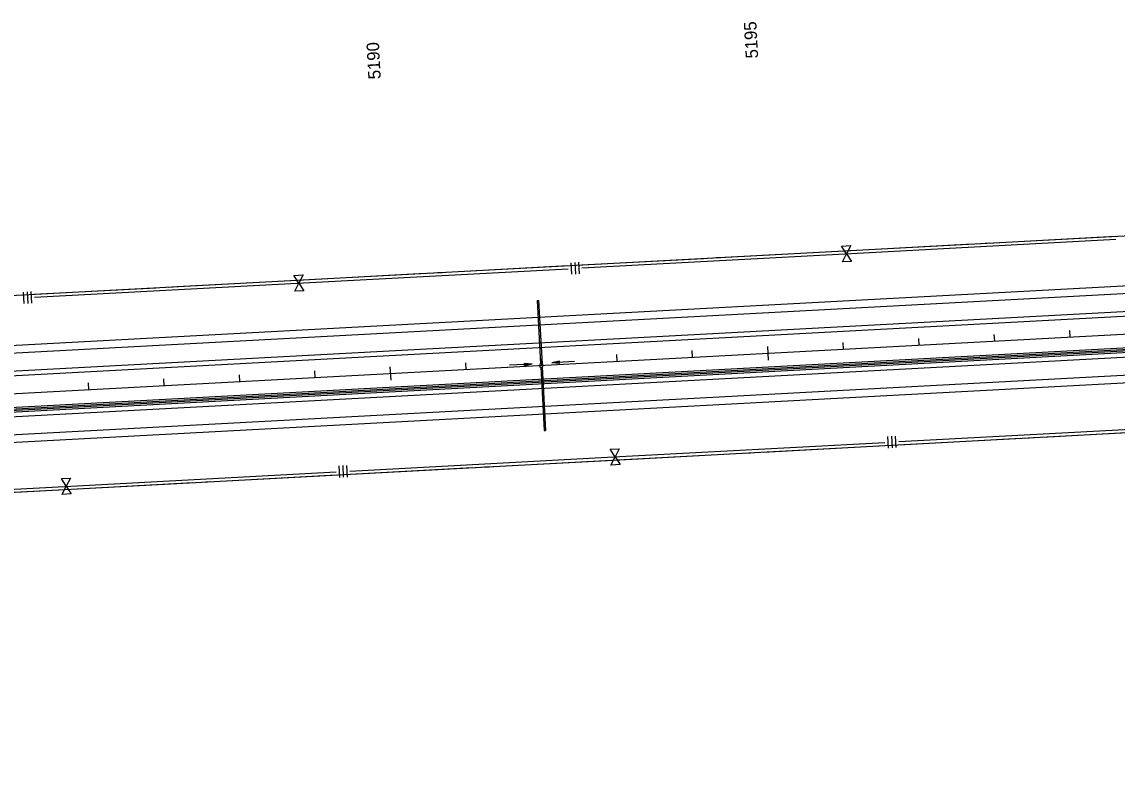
# Model space of a CAD drawing. Extents: x 192699 to 285914, y 194342 to 233219.
# Drawn here: x 263139 to 264587, y 224942 to 225937 of the extents above; entities that cross this region are included whole.
import ezdxf

# ---------------------------------------------------------------- set-up
doc = ezdxf.new("R2010")
doc.units = 0
for name, color, linetype in [('CENT LINE', 7, 'Continuous'), ('CONCRETE', 7, 'Continuous'), ('DRAINAGE', 7, 'Continuous'), ('DRAINAGE ARROWS', 7, 'Continuous'), ('R-W - CofA', 7, 'Continuous'), ('R_Water Annot', 7, 'Continuous'), ('ROAD', 7, 'Continuous'), ('SHOULDER', 7, 'Continuous'), ('STATIONING1', 7, 'Continuous'), ('WRSF', 7, 'Continuous')]:
    doc.layers.add(name, color=color, linetype=linetype)

msp = doc.modelspace()

# ---------------------------------------------------------------- linework, layer by layer
at = {"layer": 'CENT LINE'}
msp.add_line((253740.3, 224942.3), (269263.7, 225774), dxfattribs=at)
at = {"layer": 'CONCRETE'}
for p, q in [((262014.4, 225367.6), (265424.6, 225550.3)), ((262014.5, 225363.6), (265424.8, 225546.3))]:
    msp.add_line(p, q, dxfattribs=at)
at = {"layer": 'DRAINAGE'}
for p, q in [((263820.2, 225568.5), (263824.7, 225484.6)), ((263822.2, 225568.6), (263826.7, 225484.7)), ((263824.9, 225480.6), (263829.4, 225396.7)), ((263826.9, 225480.7), (263831.4, 225396.8))]:
    msp.add_line(p, q, dxfattribs=at)
for points in [[(263820.2, 225568.5), (263822.2, 225568.6)], [(263829.4, 225396.7), (263831.4, 225396.8)]]:
    msp.add_lwpolyline(points, dxfattribs=at)
msp.add_lwpolyline([(263823.9, 225480.5), (263827.9, 225480.8), (263827.7, 225484.8), (263823.7, 225484.5)], close=True, dxfattribs=at)
at = {"layer": 'DRAINAGE ARROWS'}
for p, q in [((263803.4, 225485.8), (263813.5, 225484.9)), ((263803.6, 225482.8), (263803.4, 225485.8)), ((263803.4, 225485.6), (263811.8, 225484.8)), ((263803.4, 225485.3), (263810.1, 225484.7)), ((263803.5, 225485.1), (263808.4, 225484.6)), ((263803.5, 225484.8), (263806.7, 225484.5)), ((263803.5, 225483.3), (263810.1, 225484.7)), ((263803.5, 225483.6), (263808.4, 225484.6)), ((263803.5, 225484.6), (263805.1, 225484.4)), ((263803.5, 225483.9), (263806.7, 225484.5)), ((263803.5, 225484.1), (263805.1, 225484.4)), ((263803.6, 225482.8), (263813.5, 225484.9)), ((263803.6, 225483.1), (263811.8, 225484.8)), ((263849.7, 225488.3), (263839.8, 225486.3)), ((263849.8, 225485.3), (263839.8, 225486.3)), ((263849.7, 225488.1), (263841.4, 225486.4)), ((263849.8, 225485.6), (263841.4, 225486.4)), ((263849.7, 225487.8), (263843.1, 225486.5)), ((263849.8, 225485.8), (263843.1, 225486.5)), ((263849.7, 225487.6), (263844.8, 225486.6)), ((263849.8, 225486.1), (263844.8, 225486.6)), ((263849.7, 225487.3), (263846.5, 225486.7)), ((263849.8, 225486.4), (263846.5, 225486.7)), ((263849.7, 225487.1), (263848.2, 225486.7)), ((263849.8, 225486.6), (263848.2, 225486.7)), ((263849.8, 225485.3), (263849.7, 225488.3))]:
    msp.add_line(p, q, dxfattribs=at)
at = {"layer": 'R-W - CofA'}
for p, q in [((264223, 225640.5), (264235, 225641.1)), ((264229.5, 225630.4), (264223, 225640.5)), ((264224.1, 225619.7), (264229.5, 225630.4)), ((264235, 225641.1), (264229.5, 225630.4)), ((264229.5, 225630.4), (264236.1, 225620.3)), ((263864.9, 225618.5), (263865.7, 225603.2)), ((263870, 225618.8), (263870.8, 225603.5)), ((263875.1, 225619.1), (263875.9, 225603.8)), ((264236.1, 225620.3), (264224.1, 225619.7)), ((263498.6, 225601.6), (263510.7, 225602.3)), ((263505.2, 225591.6), (263498.6, 225601.6)), ((263510.7, 225602.3), (263505.2, 225591.6)), ((263499.8, 225580.9), (263505.2, 225591.6)), ((263505.2, 225591.6), (263511.8, 225581.5)), ((263140.5, 225579.7), (263141.4, 225564.4)), ((263145.6, 225580), (263146.5, 225564.7)), ((263150.7, 225580.3), (263151.6, 225565)), ((263511.8, 225581.5), (263499.8, 225580.9)), ((264283.8, 225388.8), (264284.6, 225373.5)), ((264288.9, 225389.1), (264289.7, 225373.7)), ((264294, 225389.3), (264294.8, 225374)), ((263916.8, 225371.9), (263928.8, 225372.5)), ((263923.4, 225361.8), (263916.8, 225371.9)), ((263928.8, 225372.5), (263923.4, 225361.8)), ((263917.9, 225351), (263923.4, 225361.8)), ((263929.9, 225351.7), (263917.9, 225351)), ((263923.4, 225361.8), (263929.9, 225351.7)), ((263557.9, 225349.9), (263558.7, 225334.6)), ((263563, 225350.2), (263563.8, 225334.8)), ((263568.1, 225350.4), (263568.9, 225335.1)), ((263190.9, 225333), (263202.9, 225333.6)), ((263197.4, 225322.9), (263190.9, 225333)), ((263192, 225312.2), (263197.4, 225322.9)), ((263202.9, 225333.6), (263197.4, 225322.9)), ((263197.4, 225322.9), (263204, 225312.8)), ((263204, 225312.8), (263192, 225312.2))]:
    msp.add_line(p, q, dxfattribs=at)
for points in [[(261904.8, 225509.9), (268431.7, 225859.6)], [(264235.3, 225634.8), (264396.3, 225643.4)], [(264235.5, 225630.7), (264585.5, 225649.5)], [(264401.5, 225643.7), (264407.7, 225644)], [(264412.9, 225644.3), (264419.1, 225644.6)], [(264424.3, 225644.9), (264585.3, 225653.5)], [(263879.5, 225611.6), (264235.5, 225630.7)], [(264068.3, 225625.8), (264235.3, 225634.8)], [(263700, 225606.1), (263861, 225614.7)], [(263879.3, 225615.7), (264040.3, 225624.3)], [(264045.5, 225624.6), (264051.7, 225624.9)], [(264056.9, 225625.2), (264063.1, 225625.6)], [(261904.6, 225249.5), (268432, 225599.2)], [(261904.6, 225249.5), (268432, 225599.2)], [(263511, 225596), (263672, 225604.6)], [(263511.2, 225591.9), (263861.2, 225610.6)], [(263677.2, 225604.9), (263683.4, 225605.2)], [(263688.6, 225605.5), (263694.8, 225605.8)], [(263155, 225576.9), (263316, 225585.5)], [(263155.2, 225572.8), (263511.2, 225591.9)], [(263321.2, 225585.8), (263327.4, 225586.1)], [(263332.6, 225586.4), (263338.8, 225586.7)], [(263344, 225587), (263511, 225596)], [(264298.5, 225381.9), (264655.3, 225401)], [(264488.1, 225387.9), (264655.5, 225396.9)], [(263929.4, 225362.1), (264280.1, 225380.9)], [(264298.7, 225377.8), (264460.1, 225386.4)], [(264465.3, 225386.7), (264471.5, 225387.1)], [(264476.7, 225387.3), (264482.9, 225387.7)], [(263929.6, 225358), (264091, 225366.7)], [(264096.1, 225366.9), (264102.4, 225367.3)], [(264107.6, 225367.6), (264113.8, 225367.9)], [(264119, 225368.2), (264280.3, 225376.8)], [(263572.6, 225343), (263929.4, 225362.1)], [(263762.2, 225349.1), (263929.6, 225358)], [(263203.5, 225323.2), (263554.2, 225342)], [(263393.1, 225329.3), (263554.4, 225337.9)], [(263572.8, 225338.9), (263734.2, 225347.6)], [(263739.4, 225347.8), (263745.6, 225348.2)], [(263750.8, 225348.4), (263757, 225348.8)], [(262846.7, 225304.1), (263203.5, 225323.2)], [(263203.7, 225319.1), (263365, 225327.8)], [(263370.2, 225328.1), (263376.5, 225328.4)], [(263381.6, 225328.7), (263387.9, 225329)], [(263036.3, 225310.2), (263203.7, 225319.1)]]:
    msp.add_lwpolyline(points, dxfattribs=at)
at = {"layer": 'R_Water Annot'}
for p, q in [((263783.5, 225483.3), (263813.5, 225484.9)), ((263803.4, 225485.8), (263813.5, 225484.9)), ((263803.6, 225482.8), (263803.4, 225485.8)), ((263803.4, 225485.6), (263811.8, 225484.8)), ((263803.4, 225485.3), (263810.1, 225484.7)), ((263803.5, 225485.1), (263808.4, 225484.6)), ((263803.5, 225484.8), (263806.7, 225484.5)), ((263803.5, 225483.3), (263810.1, 225484.7)), ((263803.5, 225483.6), (263808.4, 225484.6)), ((263803.5, 225484.6), (263805.1, 225484.4)), ((263803.5, 225483.9), (263806.7, 225484.5)), ((263803.5, 225484.1), (263805.1, 225484.4)), ((263803.6, 225482.8), (263813.5, 225484.9)), ((263803.6, 225483.1), (263811.8, 225484.8)), ((263849.7, 225488.3), (263839.8, 225486.3)), ((263869.7, 225488), (263839.8, 225486.3)), ((263849.8, 225485.3), (263839.8, 225486.3)), ((263849.7, 225488.1), (263841.4, 225486.4)), ((263849.8, 225485.6), (263841.4, 225486.4)), ((263849.7, 225487.8), (263843.1, 225486.5)), ((263849.8, 225485.8), (263843.1, 225486.5)), ((263849.7, 225487.6), (263844.8, 225486.6)), ((263849.8, 225486.1), (263844.8, 225486.6)), ((263849.7, 225487.3), (263846.5, 225486.7)), ((263849.8, 225486.4), (263846.5, 225486.7)), ((263849.7, 225487.1), (263848.2, 225486.7)), ((263849.8, 225486.6), (263848.2, 225486.7)), ((263849.8, 225485.3), (263849.7, 225488.3))]:
    msp.add_line(p, q, dxfattribs=at)
at = {"layer": 'ROAD'}
for p, q in [((257860.4, 225217.1), (265550.1, 225629.1)), ((255085.2, 225044.4), (265536.9, 225604.4)), ((255121.9, 224986.3), (265503.9, 225542.5)), ((258372, 225136.4), (265490.7, 225517.8))]:
    msp.add_line(p, q, dxfattribs=at)
at = {"layer": 'SHOULDER'}
for p, q in [((257898.9, 225229.2), (265519.2, 225637.5)), ((257901, 225189.3), (264833.1, 225560.7)), ((257895.6, 225140.9), (265424.9, 225544.3)), ((258272.7, 225121.1), (265448.7, 225505.5))]:
    msp.add_line(p, q, dxfattribs=at)
at = {"layer": 'STATIONING1'}
for points in [[(264524.3, 225529.1), (264524.8, 225520.1)], [(264224.8, 225513), (264225.2, 225504.1)], [(264324.6, 225518.4), (264325.1, 225509.4)], [(264424.5, 225523.7), (264425, 225514.8)], [(263925.2, 225497), (263925.7, 225488)], [(264025, 225502.3), (264025.5, 225493.4)], [(264124.9, 225507.7), (264125.9, 225489.7)], [(263725.5, 225486.3), (263726, 225477.3)], [(263825.3, 225491.6), (263825.8, 225482.7)], [(263425.9, 225470.2), (263426.4, 225461.3)], [(263525.8, 225475.6), (263526.2, 225466.6)], [(263625.6, 225480.9), (263626.6, 225463)], [(263226.2, 225459.5), (263226.7, 225450.6)], [(263326, 225464.9), (263326.5, 225455.9)]]:
    msp.add_lwpolyline(points, dxfattribs=at)
at = {"layer": 'WRSF'}
msp.add_line((262014.4, 225365.6), (265453.9, 225549.8), dxfattribs=at)

# ---------------------------------------------------------------- texts
at = {"layer": 'STATIONING1'}
for s, p in [('5195', (264112.7, 225889)), ('5190', (263613.5, 225861.6))]:
    msp.add_text(s, height=16.5, rotation=93.0667, dxfattribs=at).set_placement(p)

doc.saveas('drawing.dxf')
